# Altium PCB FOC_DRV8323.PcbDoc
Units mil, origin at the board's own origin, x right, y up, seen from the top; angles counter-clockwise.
Board outline 2192.91 x 943.98 mil, 4 copper layers (Top Layer, GND, Sign, Bottom Layer), stack 23.756 mil thick; 72 components, 67 nets, 296 pads, 257 vias.
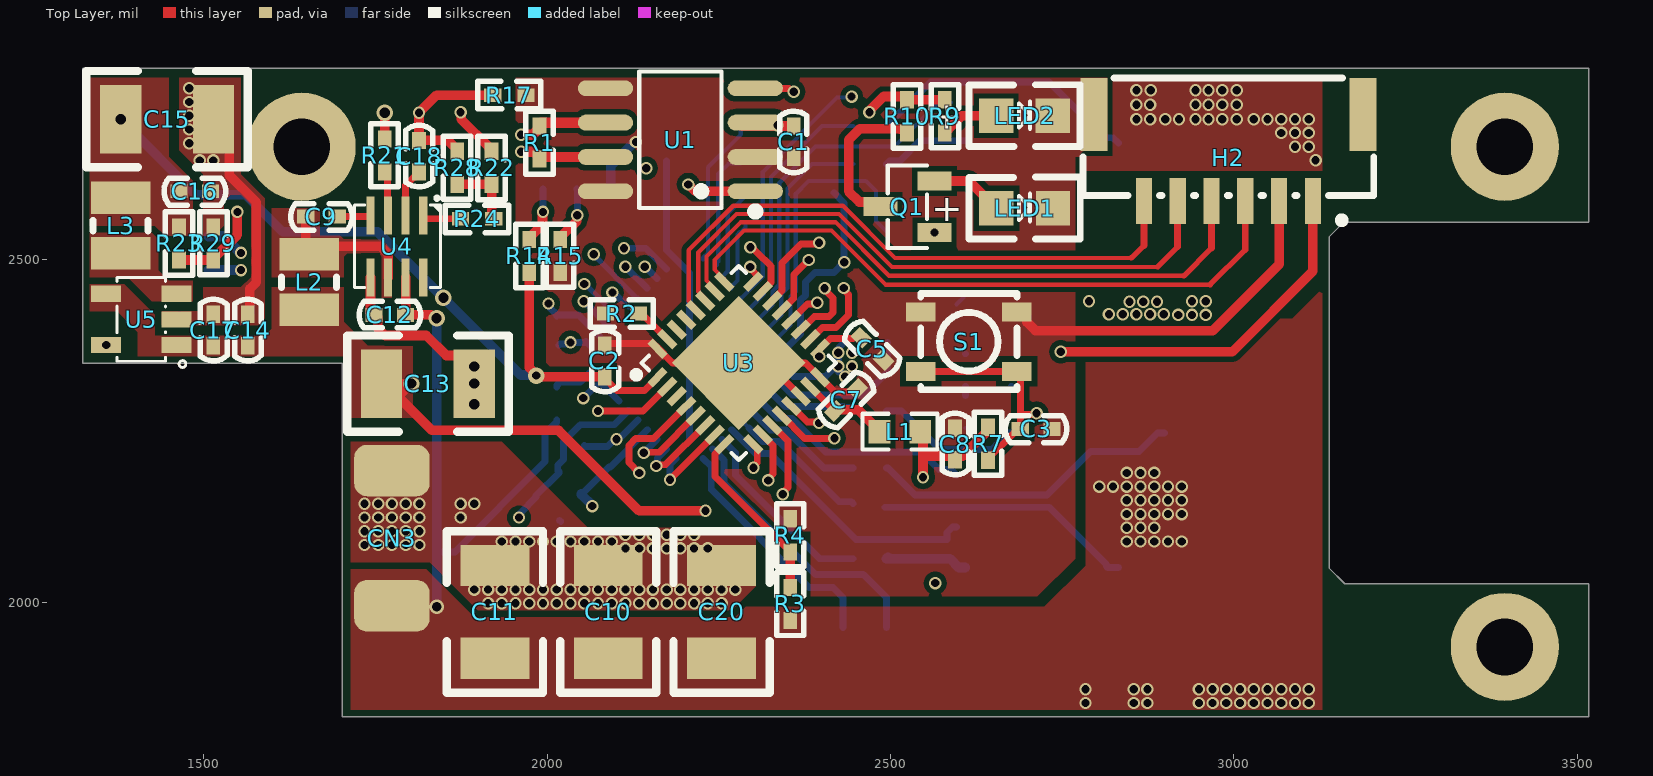
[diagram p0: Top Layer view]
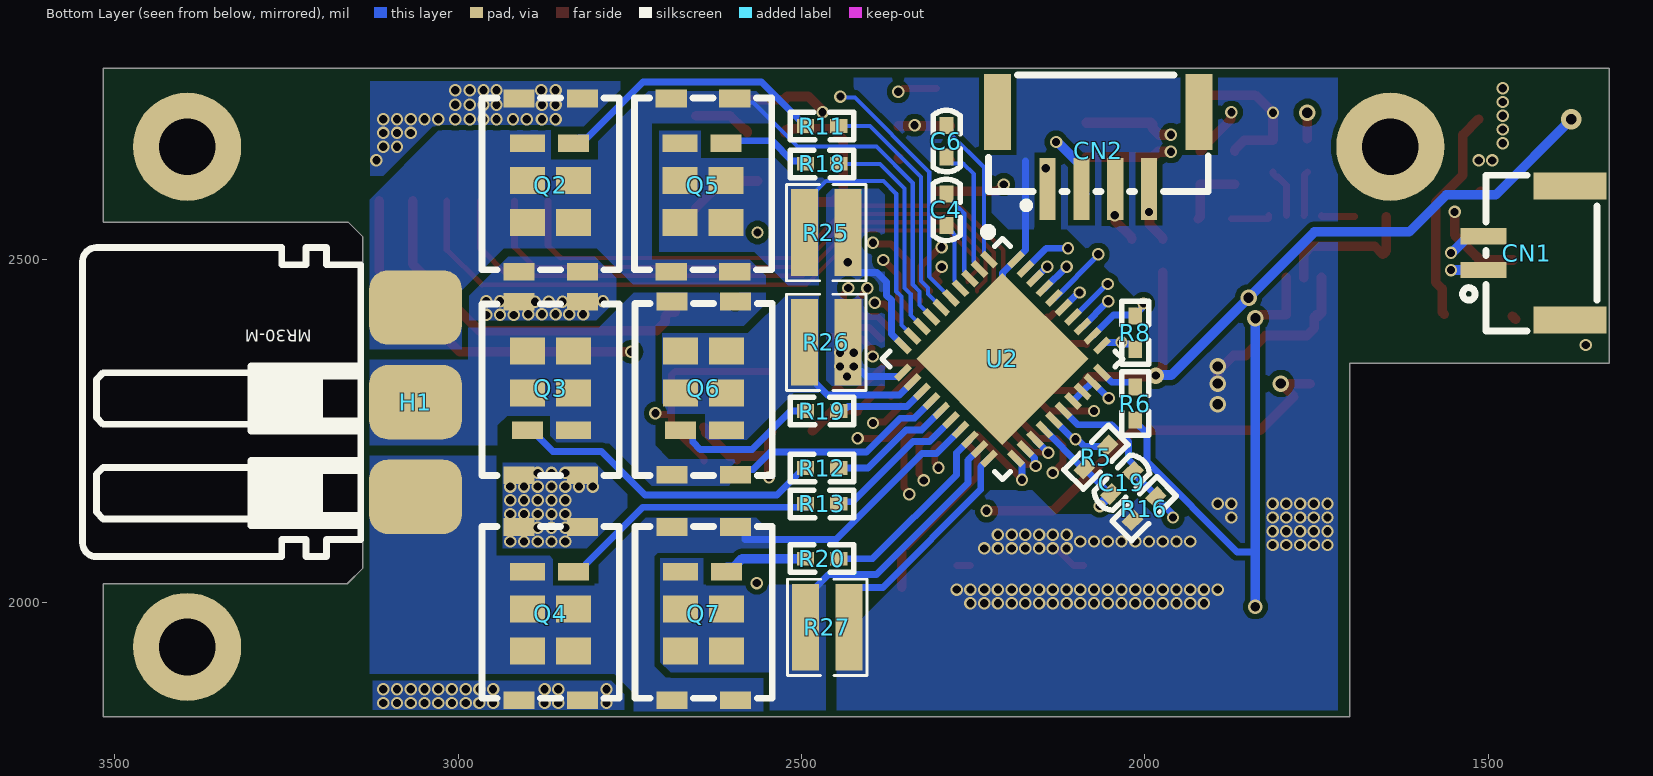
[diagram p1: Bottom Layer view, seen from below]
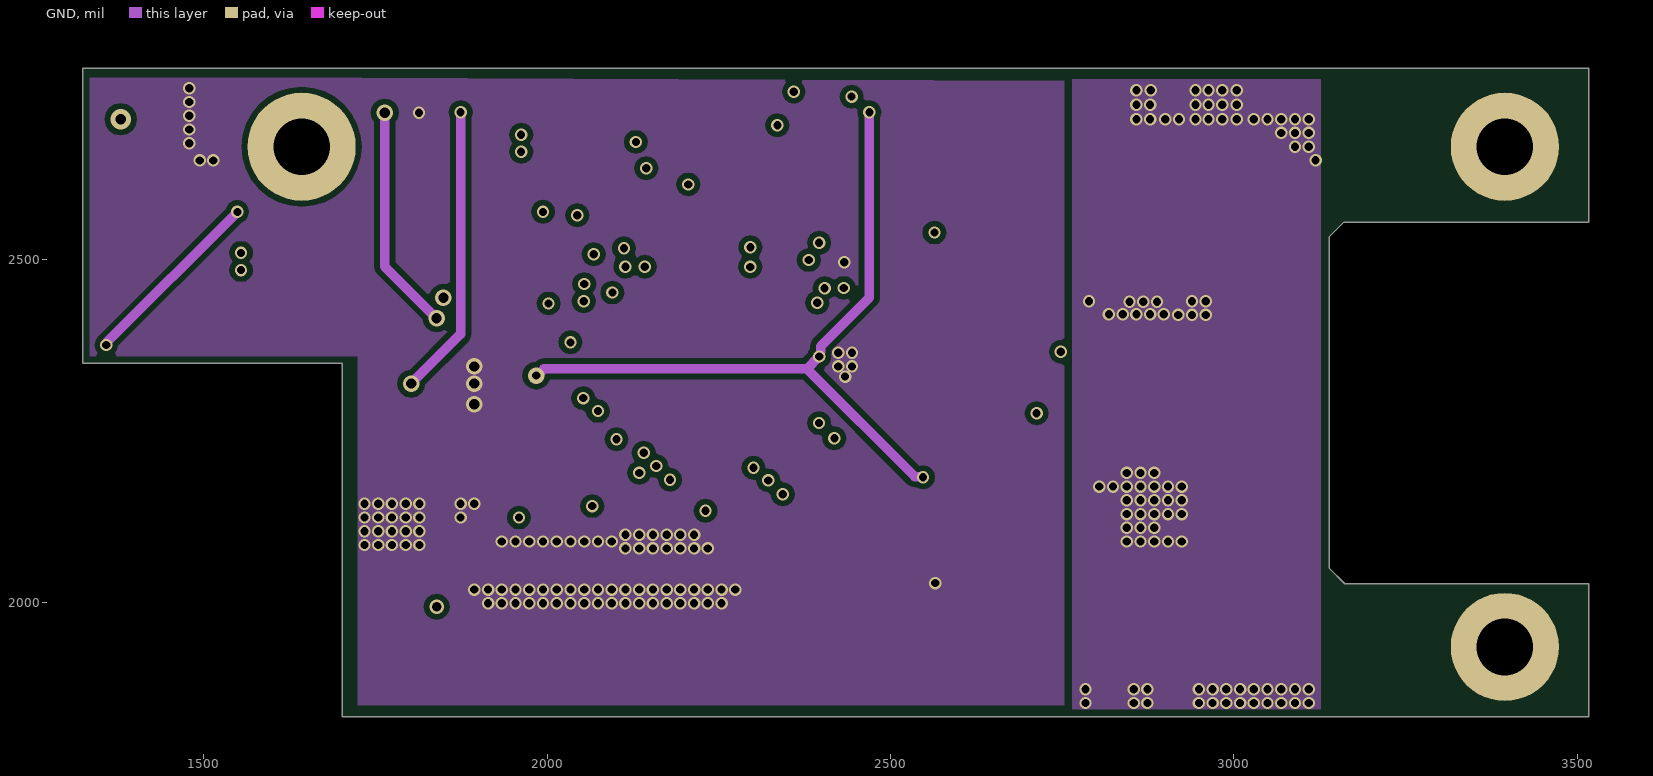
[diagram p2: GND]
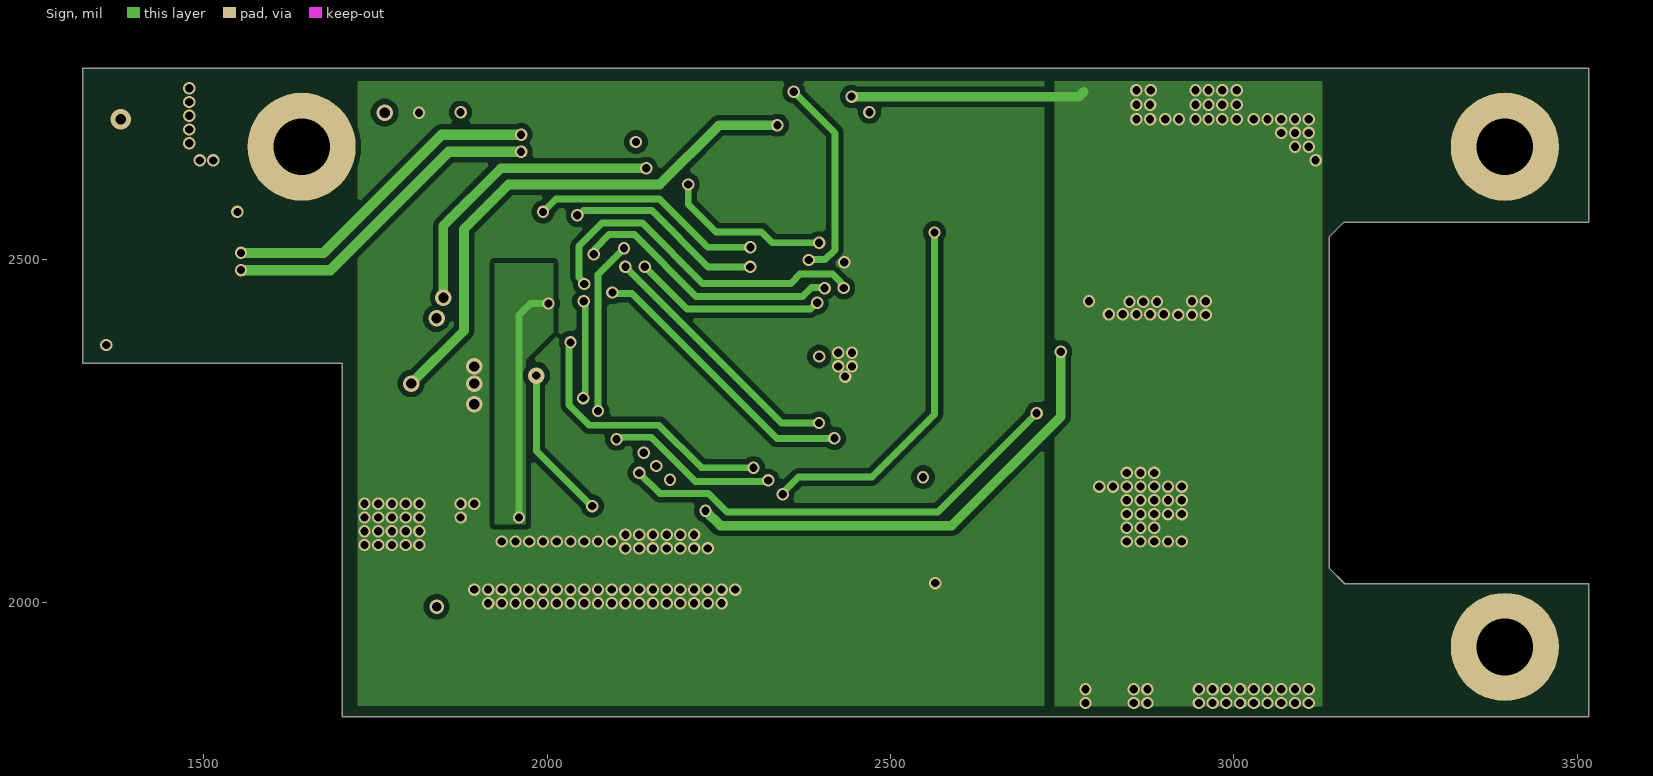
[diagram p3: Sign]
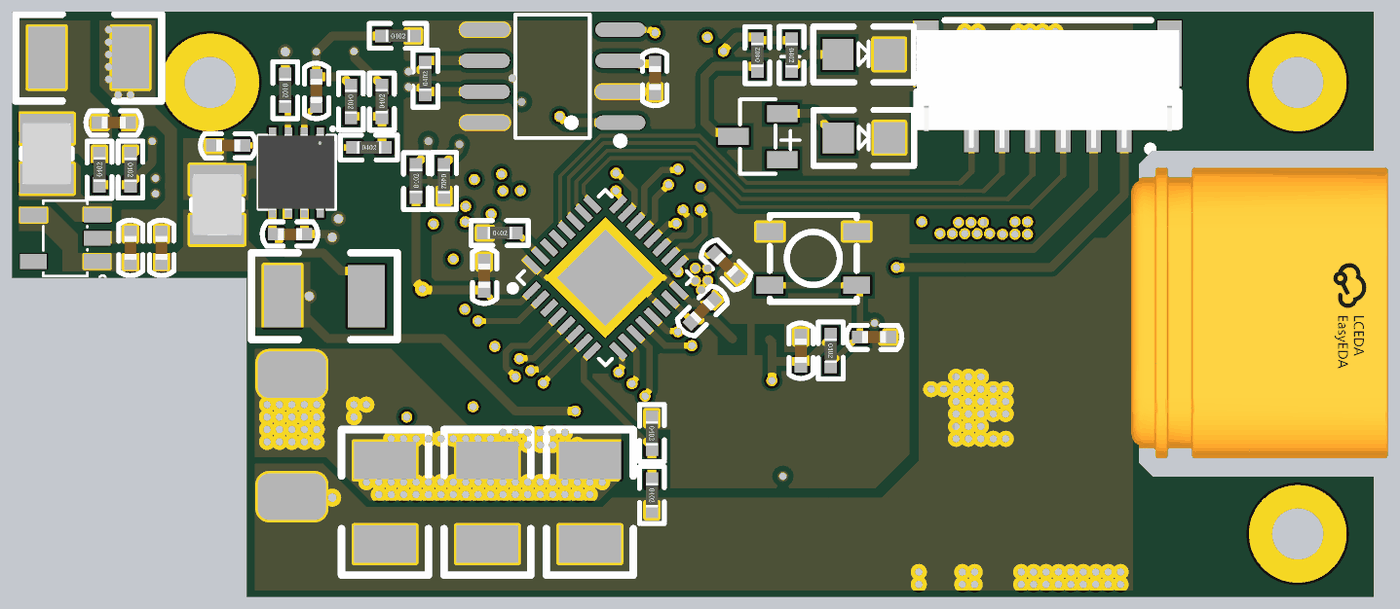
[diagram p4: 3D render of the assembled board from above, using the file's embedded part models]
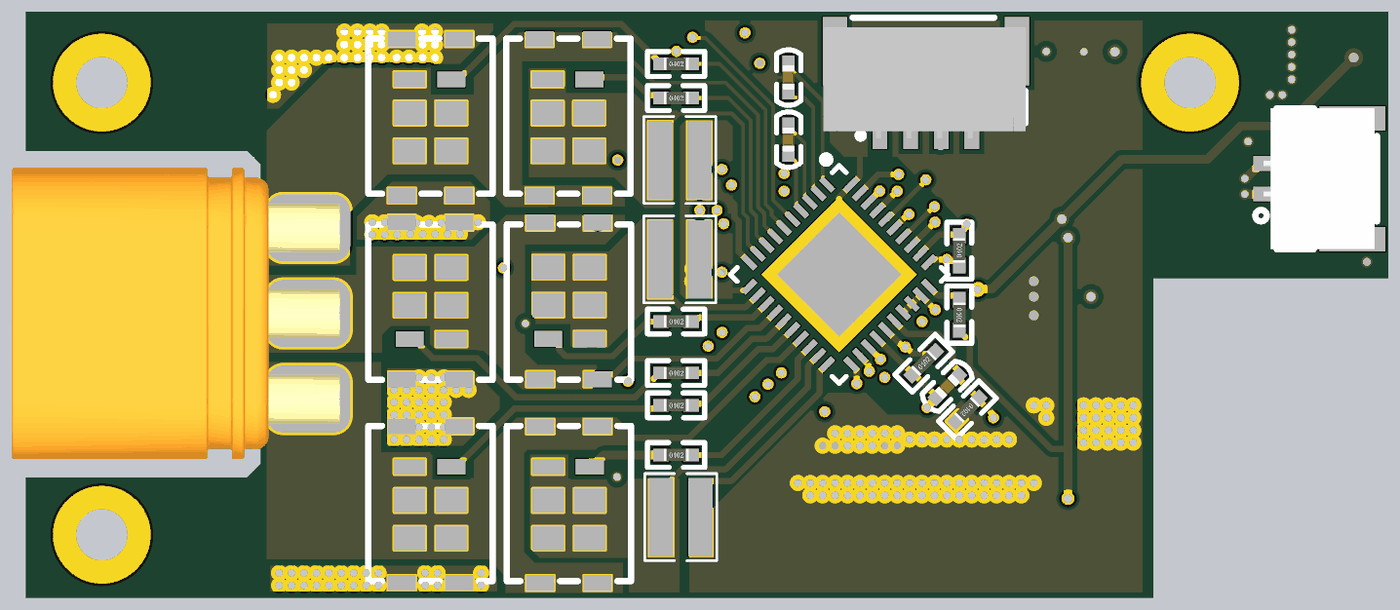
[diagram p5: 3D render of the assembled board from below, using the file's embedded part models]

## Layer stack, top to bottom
Top Solder: solder mask 0.4, Solder Resist, Dk 3.5
Top Layer: signal copper 1.4
Dielectric 2: prepreg 2.8, PP-006, Dk 4.1
GND: signal copper 1.378
Dielectric 1: dielectric 12.6, FR-4, Dk 4.8
Sign: signal copper 1.378
Dielectric 3: prepreg 2.8, PP-006, Dk 4.1
Bottom Layer: signal copper 1.4
Bottom Solder: solder mask 0.4, Solder Resist, Dk 3.5

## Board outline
1701.6,1834.03 1701.6,2348.88 1323.65,2348.88 1323.65,2778.02 3516.56,2778.02 3516.56,2553.61 3159.74,2553.61 3138.61,2532.47 3138.61,2050.37 3161.42,2027.56 3516.56,2027.56 3516.56,1834.03

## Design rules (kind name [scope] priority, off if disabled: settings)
Clearance [All] p1: gap=6 ignorepadtopadclearanceinfootprint=FALSE except(0: Arc-Hole Track-Hole SMDPad-Hole THPad-Hole Via-Hole Fill-Hole Poly-Hole Region-Hole Text-Hole; 8: Arc-Fill Arc-Poly Arc-Region Track-Fill Track-Poly Track-Region SMDPad-Fill SMDPad-Poly SMDPad-Region THPad-Fill THPad-Poly THPad-Region Via-Fill Via-Poly Via-Region Fill-Fill Fill-Poly Fill-Region Poly-Poly Poly-Region Region-Region)
DiffPairsRouting [All] p1: maxlimit=10 minlimit=10 mostfreqgap=10 toplayer_minwidth=15 toplayer_maxwidth=15 toplayer_prefwidth=15 midlayer1_minwidth=15 midlayer1_maxwidth=15 midlayer1_prefwidth=15 midlayer2_minwidth=15 midlayer2_maxwidth=15 midlayer2_prefwidth=15 bottomlayer_minwidth=15 bottomlayer_maxwidth=15 bottomlayer_prefwidth=15 maxuncoupledlength=500
HoleToHoleClearance [All] p1: gap=4 allowstackedmicrovias=TRUE
MinimumSolderMaskSliver [All] p1: minsoldermaskwidth=0
PlaneClearance [All] p1: clearance=8
PlaneConnect [All] p1: planeconnectstyle=Direct reliefexpansion=20 reliefentries=4 reliefconductorwidth=10 reliefairgap=10
PolygonConnect [All] p1: connectstyle=Direct reliefconductorwidth=10 reliefentries=4 polygonreliefangle="90 Angle" airgapwidth=10
RoutingVias [All] p1: holewidth=12 width=18 viastyle="Through Hole" minholewidth=10 minwidth=18 maxholewidth=28 maxwidth=50
SilkToSilkClearance [All] p1: silktosilkclearance=0
SilkToSolderMaskClearance [IsPad] p1: minsilkscreentomaskgap=0 clearancetoexposedcopper=TRUE
SolderMaskExpansion [All] p1: expansion=4 istentingtop=FALSE
Width [All] p1: maxlimit=14 minlimit=6 preferedwidth=10
23 further rules are at their usual default settings.

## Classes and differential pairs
differential pair CAN: +CAN_P -CAN_N

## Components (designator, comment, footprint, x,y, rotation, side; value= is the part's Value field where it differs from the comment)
C1 "100nF" c0402 2359,2649 r90 top
C2 "100nF" c0402 2084,2374 r270 top
C3 "100nF" c0402 2734,2253 r180 top
C4 "1uF" c0402 2289,2594.05 r270 bottom
C5 "100nF" c0402 2489,2354 r135 top
C6 "47nF" c0402 2289,2694 r270 bottom
C7 "100nF" c0402 2450.82,2310.82 r225 top
C8 "100nF" c0402 2594,2253 r270 top
C9 "100nF" c0402 1693.43,2562.19 r180 top
C10 "10uF" 1210 2089,2054 r270 top
C11 "10uF" 1210 1924,2054 r270 top
C12 "100nF" c0402 1749,2419 r0 top
C13 "10uF" 1210 1894,2319 r180 top
C14 "100nF" c0402 1564,2419 r270 top
C15 "10uF" 1210 1514,2704 r180 top
C16 "100nF" c0402 1509,2599 r180 top
C17 "1uF" c0402 1514,2419 r270 top
C18 "100nF" c0402 1813.43,2672.19 r270 top
C19 "100nF" c0402 2049,2159 r135 bottom
C20 "10uF" 1210 2254,2054 r270 top
CN1 "卧式CAN" "GH1.25 2P 卧式" 1444,2509 r90 bottom
CN2 "卧式STLINK" CONN-SMD_4P-P1.25_GH1.25-4P 2067.77,2658.35 r0 bottom
CN3 "XT30_1" XT30卧式焊盘 1774,2094 r0 top
H1 "MR30-M" MR30 3062,2292 r270 bottom
H2 "卧式GH1.25 6PIN" CONN-SMD_6P-P1.25_XYECONN_XY-GH1.25-6A61 2991.95,2648.1 r180 top
L1 "1008屏蔽电感" R0603 3878.19,2290.01 r180 top
L2 "1008屏蔽电感" IND-SMD_L2.5-W2.0 1653.43,2466.71 r90 top
L3 "1008屏蔽电感" IND-SMD_L2.5-W2.0 1379,2549 r270 top
LED1 "LED" led0805 2654.2,2574.35 r0 top
LED2 "LED" led0805 2654,2709 r0 top
Q1 "SS8050" SOT-23-3_L2.9-W1.3-P1.90-LS2.4-BR 2305.65,2731.51 r0 top
Q2 "IRF7480MTRPBF" TRS-SMD_IRF7480MTRPBF 2865.3,2607.9 r270 bottom
Q3 "IRF7480MTRPBF" TRS-SMD_IRF7480MTRPBF 2865.3,2312.03 r90 bottom
Q4 "IRF7480MTRPBF" TRS-SMD_IRF7480MTRPBF 2865.3,1983.98 r270 bottom
Q5 "IRF7480MTRPBF" TRS-SMD_IRF7480MTRPBF 2643.36,2607.9 r270 bottom
Q6 "IRF7480MTRPBF" TRS-SMD_IRF7480MTRPBF 2642.47,2312.31 r90 bottom
Q7 "IRF7480MTRPBF" TRS-SMD_IRF7480MTRPBF 2642.47,1983.98 r270 bottom
R1 "120Ω" R0402 1989,2645.8 r90 top
R2 "10K" R0402 2084.8,2421 r0 top
R3 "10K" R0402 2354,2022.2 r270 top
R4 "1K" R0402 2354,2122.2 r270 top
R5 "200k" R0402 2088.08,2194.92 r135 bottom
R6 "200k" R0402 2014,2314 r270 bottom
R7 "10K" R0402 2642,2255.5 r270 top
R8 "200k" R0402 2014,2369 r90 bottom
R9 "2K" R0402 2579,2732.2 r270 top
R10 "2KΩ" R0402 2524,2684 r90 top
R11 "2.2R" R0402 2494,2694 r180 bottom
R12 "2.2R" R0402 2494,2196.01 r180 bottom
R13 "2.2R" R0402 2494,2144 r180 bottom
R14 "10KΩ" R0402 1974,2480.8 r90 top
R15 "10KΩ" R0402 2019,2529 r270 top
R16 "0" R0402 1984,2154 r315 bottom
R17 "0" R0402 1920.8,2739 r0 top
R18 "2.2R" R0402 2494,2639 r180 bottom
R19 "2.2R" R0402 2494,2279 r180 bottom
R20 "2.2R" R0402 2494,2064 r180 bottom
R21 "10KΩ" R0402 1763.43,2675.39 r270 top
R22 "43KΩ" R0402 1919,2609 r90 top
R23 "232KΩ" R0402 1464,2499 r90 top
R24 "51KΩ" R0402 1874,2559 r0 top
R25 "0.001" R0612 2464,2539 r0 bottom
R26 "0.001" R0612 2464,2379 r0 bottom
R27 "0.001" R0612 2462.5,1964 r0 bottom
R28 "8.2KΩ" R0402 1869,2657.2 r270 top
R29 "51KΩ" R0402 1514,2547.2 r270 top
S1 "SW" KEY_SMD 2614,2380 r180 top
U1 "SN65HVD1050DR" SOIC-8_L4.9-W3.9-P1.27-LS6.0-BL 2194,2674 r90 top
U2 "DRV8323HRTAR" QFN-40_L6.0-W6.0-P0.50-BL-EP4.5 2215.52,2362.96 r315 bottom
U3 "STM32G431KBU3" UFQFPN-32_L5.0-W5.0-P0.50-BL-EP3.5 2275.98,2345.98 r315 top
U4 "MP9943" "QFN-8 3x3" 1819.59,2564 r270 top
U5 "TLV62569DBVR" SOT-23-5_L3.0-W1.7-P0.95-LS2.8-BR 1409,2409 r0 top

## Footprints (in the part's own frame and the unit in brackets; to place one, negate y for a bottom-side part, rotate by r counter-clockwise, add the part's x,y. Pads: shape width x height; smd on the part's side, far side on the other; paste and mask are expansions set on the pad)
1210 [mil]
  rect 60x100 smd: 1(0,0) 2(135,0)
  silkscreen extent -50,-70 185,70, body extent 4,-49 130,49, height 30
c0402 [mil]
  rect 25x20 smd: 1(-1,0) 2(45,0)
  silkscreen extent -23,-19 67,20, body extent 2,-10 42,10, height 20
CONN-SMD_4P-P1.25_GH1.25-4P [mm]
  rect 0.6x2.3 smd mask+0.051: 1(1.875,1.425) 2(0.625,1.425) 3(-0.625,1.425) 4(-1.875,1.425)
  rect 1x2.8 smd mask+0.051: 5(-3.725,-1.425) 6(3.725,-1.425)
  silkscreen extent -4.06,-2.8 4.06,2.16, body extent -4.07,-2.4 4.19,2.15, height 4.13
CONN-SMD_6P-P1.25_XYECONN_XY-GH1.25-6A61 [mm]
  rect 0.6x1.7 smd paste+0 mask+0.05: 1(-3.125,1.6) 2(-1.875,1.6) 3(-0.625,1.6) 4(0.625,1.6) 5(1.875,1.6) 6(3.125,1.6)
  rect 1x2.7 smd paste+0 mask+0.05: 7(4.975,-1.6) 8(-4.975,-1.6)
  silkscreen extent -5.38,-2.95 5.38,2.44, body extent -5.38,-2.55 5.39,2.3, height 4.34
"GH1.25 2P 卧式" [mm]
  rect 0.6x1.7 smd mask+0.051: 1(-0.625,1.602) 2(0.625,1.602)
  rect 1x2.7 smd mask+0.051: 3(2.475,-1.602) 4(-2.475,-1.598)
  silkscreen extent -2.88,-2.6 2.88,2.37, body extent -2.88,-2.51 2.88,2.05, height 4.13
IND-SMD_L2.5-W2.0 [mm]
  rect 1.2x2.2 smd: 1(1.028,0) 2(-1.028,0)
  silkscreen extent -0.2,-1.02 0.2,1.02, body extent -1.26,-1 1.26,1, height 1.2
KEY_SMD [mm]
  rect 1.1x0.7 smd: 1(-1.775,-1.1) 1(1.775,-1.1) 2(-1.775,1.1) 2(1.775,1.1)
  silkscreen extent -1.78,-1.78 1.78,1.78
led0805 [mil] "1/8W"
  rect 50x50 smd: 1(0,0) 2(82.3,0.2)
  silkscreen extent -40,-45 122,45, body extent 2,-25 80,25, height 20
MR30 [mm]
  rrect50% 2.75x3.429 smd: 1(3.5,0) 2(0,0) 3(-3.5,0)
  silkscreen extent -5.72,-12.31 5.71,-2.02, body extent -5.95,-12.12 5.95,1.28, height 2.45
"QFN-8 3x3" [mm]
  rect 1.4x0.3 smd: 1(0,0) 2(0,-0.65) 3(0,-1.3) 4(0,-1.95) 5(2.3,-1.95) 6(2.3,-1.3) 7(2.3,-0.65) 8(2.3,0)
  silkscreen extent -0.64,-2.54 2.67,0.64, body extent -0.41,-2.53 2.69,0.57, height 0.94
QFN-40_L6.0-W6.0-P0.50-BL-EP4.5 [mm]
  rect 0.25x0.7 smd paste-100 mask+0.051: 1(-2.25,-2.659) 2(-1.75,-2.659) 3(-1.25,-2.659) 4(-0.75,-2.659) 5(-0.25,-2.659) 6(0.25,-2.659) 7(0.75,-2.659) 8(1.25,-2.659) 9(1.75,-2.659) 10(2.25,-2.659) 21(2.25,3.241) 22(1.75,3.241) 23(1.25,3.241) 24(0.75,3.241) 25(0.25,3.241) 26(-0.25,3.241) 27(-0.75,3.241) 28(-1.25,3.241) 29(-1.75,3.241) 30(-2.25,3.241)
  rect 0.7x0.25 smd paste-100 mask+0.051: 11(2.95,-1.958) 12(2.95,-1.459) 13(2.95,-0.958) 14(2.95,-0.459) 15(2.95,0.042) 16(2.95,0.541) 17(2.95,1.042) 18(2.95,1.541) 19(2.95,2.041) 20(2.95,2.541) 31(-2.95,2.541) 32(-2.95,2.041) 33(-2.95,1.541) 34(-2.95,1.042) 35(-2.95,0.541) 36(-2.95,0.042) 37(-2.95,-0.459) 38(-2.95,-0.958) 39(-2.95,-1.459) 40(-2.95,-1.958)
  rect 4.5x4.5 smd paste-100 mask+0.051: 41(0,0.292)
  silkscreen extent -3.15,-3.56 3.15,3.44
R0402 [mil] "1/16W"
  rect 25x20 smd: 1(0,0) 2(48.2,0)
  silkscreen extent -22,-20 70,20, body extent 5,-10 44,10, height 14
R0603 [mil]
  rect 31.75x34.02 smd paste-3937.01 mask+2: 1(1334.87,41.01) 2(1394.19,41.01)
  silkscreen extent 1310,15 1419,67, body extent 1334,24 1396,56, height 18
R0612 [mm]
  rect 1x3.2 smd paste+0 mask+0.051: 1(-0.8,0) 2(0.8,0)
  silkscreen extent -1.47,-1.78 1.47,1.78
SOIC-8_L4.9-W3.9-P1.27-LS6.0-BL [mm]
  oval 0.588x2.045 smd mask+0.051: 1(-1.905,-2.772) 2(-0.635,-2.772) 3(0.635,-2.772) 4(1.905,-2.772) 5(1.905,2.772) 6(0.635,2.772) 7(-0.635,2.772) 8(-1.905,2.772)
  silkscreen extent -2.8,-2.92 2.53,1.52, body extent -2.45,-3 2.45,3, height 1.75
SOT-23-3_L2.9-W1.3-P1.90-LS2.4-BR [mm]
  rect 1.25x0.7 smd: 1(6.562,-4.885) 2(6.562,-2.985) 3(4.562,-3.935)
  silkscreen extent 4.84,-5.46 6.29,-2.41, body extent 4.19,-5.39 6.99,-2.49, height 1.3
SOT-23-5_L3.0-W1.7-P0.95-LS2.8-BR [mm]
  rect 1.1x0.6 smd paste+0 mask+0.051: 1(1.3,-0.861) 2(1.3,0.089) 3(1.3,1.039) 4(-1.3,1.039) 5(-1.3,-0.861)
  silkscreen extent -0.9,-1.69 1.65,1.64
TRS-SMD_IRF7480MTRPBF [mm]
  rect 0.65x1.15 smd paste+0 mask+0.051: 1(-1.555,0.85) 7(-3.205,1.175) 8(-3.205,-1.175) 9(3.205,-1.175) 10(3.205,1.175)
  rect 1x1.3 smd paste+0 mask+0.051: 2(-0.175,0.85) 3(1.375,0.85) 4(1.375,-0.85) 5(-0.175,-0.85)
  rect 0.65x1.3 smd paste+0 mask+0.051: 6(-1.555,-0.85)
  silkscreen extent -3.22,-2.54 3.13,2.54
UFQFPN-32_L5.0-W5.0-P0.50-BL-EP3.5 [mm]
  rect 0.28x0.8 smd paste-100 mask+0.051: 1(-1.75,-2.392) 2(-1.25,-2.392) 3(-0.75,-2.392) 4(-0.25,-2.392) 5(0.25,-2.392) 6(0.75,-2.392) 7(1.25,-2.392) 8(1.75,-2.392) 17(1.75,2.609) 18(1.25,2.608) 19(0.75,2.609) 20(0.25,2.608) 21(-0.25,2.608) 22(-0.75,2.608) 23(-1.25,2.608) 24(-1.75,2.608)
  rect 0.8x0.28 smd paste-100 mask+0.051: 9(2.5,-1.642) 10(2.5,-1.142) 11(2.5,-0.642) 12(2.5,-0.142) 13(2.5,0.358) 14(2.5,0.858) 15(2.5,1.358) 16(2.5,1.858) 25(-2.5,1.858) 26(-2.5,1.358) 27(-2.5,0.858) 28(-2.5,0.358) 29(-2.5,-0.142) 30(-2.5,-0.642) 31(-2.5,-1.142) 32(-2.5,-1.642)
  rect 3.5x3.5 smd paste-100 mask+0.051: 33(0,0.108)
  silkscreen extent -2.54,-3.01 2.54,2.65
XT30卧式焊盘 [mil]
  rrect50% 110x75 smd: 1(0,98.43) 2(0,-98.43)

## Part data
C1 C9 C12 C14 C15 C16 C17 C18: library part 0402贴片电容, "贴片电容0402"
C2 C3 C4 C5 C6 C7 C8 C19: library part CC0201JRX7R9BB101
C10 C11 C13 C20: library part 1210贴片电容, "1210贴片电容"
H1: BOM_Manufacturer=AMASS(艾迈斯)
LED1 LED2: library part 0805贴片LED, "0805贴片LED"
Q1: library part 2N2222, "三极管"
R1 R10 R14 R15 R21 R22 R23 R24 R28 R29: library part 0402贴片电阻, "0402贴片电阻"
R2 R3 R4 R5 R6 R7 R8 R9 R16 R17: library part 2.2R, BOM_Manufacturer=UniOhm, BOM_Manufacturer Part=0603WAJ022JT5E
R11 R12 R13 R18 R19 R20: BOM_Manufacturer=UniOhm, BOM_Manufacturer Part=0603WAJ022JT5E
R25 R26 R27: library part 0.0005, BOM_Manufacturer=RALEC(旺诠), BOM_Manufacturer Part=LR2512-23R0005J4
S1: "开关"
U1: "CAN芯片", JLCPCB Part Class="Extended Part", LCSC Part Name=4.5V~5.5V, Manufacturer=TI(德州仪器), Operating Temperature=-40℃~+125℃, Supply Current=50mA

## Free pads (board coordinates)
  round 157.48 hole 82.68: 2(1642.54,2663.84) 2(3394.51,1935.5) 2(3394.51,2663.84)

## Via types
v1: diameter 18, hole 12, Top Layer to Bottom Layer, 226 vias
v2: diameter 18, hole 12, Top Layer to Bottom Layer, tented both sides, 21 vias
v3: diameter 24, hole 15, Top Layer to Bottom Layer, tented both sides, 7 vias
v4: diameter 24, hole 12, Top Layer to Bottom Layer, 1 vias
v5: diameter 30, hole 15, Top Layer to Bottom Layer, tented both sides, 1 vias
v6: diameter 21, hole 14, Top Layer to Bottom Layer, 1 vias

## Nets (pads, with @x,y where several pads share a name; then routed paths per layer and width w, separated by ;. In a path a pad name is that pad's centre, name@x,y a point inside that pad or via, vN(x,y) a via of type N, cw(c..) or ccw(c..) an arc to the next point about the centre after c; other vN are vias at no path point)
5V: C1.2 C13.2 C14.2 C17.2 H2.1 L2.2 R22.2 U1.3 U5.1 U5.4 | length 3195.3
  Top Layer w10: U1.3@2283.15,2694 2283.7,2694.55 2334.73,2694.55 v1(2335.28,2695.09)
  Top Layer w14: C13.2 v3(1802.04,2319) 1783.02,2299.98 1832.12,2250.88 2016.84,2250.88 2134.03,2133.69 v1(2230.64,2133.69) ; v2(1874,2714) 1874.77,2713.23 1874.77,2703.93 1916,2662.7 1916,2660.2 R22.2 ; U1.3@2283.15,2694 C1.2 ; v1(2747.98,2365.33) 2997.57,2365.33 3114.98,2482.74 H2.1
  GND w14: v3(1802.04,2319) 1874,2390.96 v2(1874,2714)
  Sign w14: v3(1802.04,2319) 1879,2395.96 1879,2544 1943.83,2608.83 2163.91,2608.83 2250.18,2695.09 v1(2335.28,2695.09) ; v1(2230.64,2133.69) 2252.17,2112.16 2589.16,2112.16 2747.98,2270.98 v1(2747.98,2365.33)
+3.3V: C2.2 C5.2 C8.2 C15.2 C16.2 C19.1 CN2.1 L1.1 L3.2 R5.1 R7.1 R9.1 R10.2 R14.1 R23.2 U2.24 U3.1 U3.17 | length 3341.7
  Top Layer w10: C2.2@2084,2326.5 2101.5,2309 2141.56,2309 U3.1 ; U3.17 2398.04,2369.89 2412.7,2384.55 2445.31,2384.55 2448.34,2387.59 2455.41,2387.59 C5.2
  Top Layer w14: R14.1 1974,2342.04 1984.25,2331.79 v4(1984.25,2330.71) 1985.33,2330.71 1987.04,2329 2081,2329 2083.5,2326.5 C2.2@2084,2326.5 ; v1(2469.26,2714.24) 2470.02,2715.01 2470.02,2717.14 2489.89,2737 2521,2737 2524,2734 R10.2 R9.1 ; L1.1 2547.33,2244.99 2547.33,2213.5 ; v1(2547.33,2182.76) 2547.33,2213.5 ; C8.2 C8.2@2594,2210.5 ; R7.1 2639,2252.5 2639,2247.5 2605,2213.5 2597,2213.5 C8.2@2594,2210.5 ; 2547.33,2213.5 2591,2213.5 C8.2@2594,2210.5
  GND w14: v4(1984.25,2330.71) 1985.33,2330.71 1995.2,2340.57 2378.22,2340.57 ; v1(2396.12,2358.47) 2378.22,2340.57 ; v1@2398.58,2364.74 2398.58,2373.58 2469.26,2444.26 v1@2469.26,2713.63 ; v1(2547.33,2182.76) 2546.56,2183.53 2535.26,2183.53 2378.22,2340.57
  Sign w10: v4(1984.25,2330.71) 1984.25,2220.96 2064.55,2140.66 v1(2065.86,2140.66)
  Sign w14: v3(1849,2444) 1849,2549 1932.45,2632.45 v2(2144.17,2632.45)
  Bottom Layer w10: C19.1 2050.58,2158.29 2089.94,2197.65 2091.97,2197.65 U2.24
  Bottom Layer w14: v5(1379,2704) 1489,2594 1561,2594 1615,2540 1753,2540 1961.53,2331.47 1983.49,2331.47 v4(1984.25,2330.71) ; C19.1 2049.71,2157.56 2065.86,2141.4 v1(2065.86,2140.66)
AGND: C19.2 R8.2 R16.1 U2.26 U2.32 | length 696.5
  Sign w10: v1(1959,2124) 1959,2419 1975.65,2435.65 v1(2002.06,2435.65)
  Bottom Layer w10: v1(1959,2124) 1960.15,2125.15 1960.15,2130.15 R16.1 1984,2155.82 2017.18,2189 C19.2 2015.41,2192.59 2015.41,2199.66 2024.08,2208.33 2024.08,2234.93 2048.15,2259 2097.64,2259 U2.26 ; v1(2002.06,2435.65) 2003.59,2434.12 2003.59,2430.11 2014,2419.7 R8.2 2015.8,2419 2045.81,2419 U2.32
CAL: R8.1 U2.31 U3.9 | length 488.7
  Top Layer w10: U3.9 2307.11,2223.43 2307.11,2222.71 2305.99,2221.59 2305.99,2204.2 2300.43,2198.63 v1(2300.43,2196.47)
  Sign w10: v1(2034,2379) 2032.47,2377.47 2032.47,2371.81 2032.02,2371.36 2032.02,2288.17 2061.92,2258.27 2163.24,2258.27 2225.04,2196.47 v1(2300.43,2196.47)
  Bottom Layer w10: R8.1@2017.41,2374.91 2019,2376.5 2029.88,2376.5 2033.86,2380.49 v1@2034,2380.49 ; v1(2034,2379) 2054.89,2379 2056.38,2380.49 2056.49,2380.49 U2.31
CAN_N: CN1.2 R1.2 U1.6 | length 669.6
  Top Layer w15: v2(1962.09,2681.5) 1979,2681.5 1989,2691.5 R1.2 1989,2696.5 1991.5,2699 U1.6
  Sign w15: v2(1554.32,2509.29) 1566.79,2509.29 1567.04,2509.05 1674,2509.05 1846.45,2681.5 v2(1962.09,2681.5)
  Bottom Layer w15: CN1.2 1528.72,2533.61 1552.46,2509.87 1553.74,2509.87 v2(1554.32,2509.29)
CAN_P: CN1.1 R1.1 U1.7 | length 656.3
  Top Layer w15: v2(1962.09,2656.5) 1980.8,2656.5 1989,2648.3 R1.1@1989,2646.5 ; R1.1 R1.1@1989,2646.5 ; U1.7 1991.5,2649 R1.1@1989,2646.5
  Sign w15: v2(1554.32,2484.29) 1554.56,2484.05 1684.36,2484.05 1856.81,2656.5 1949.61,2656.5 v2(1962.09,2656.5)
  Bottom Layer w15: CN1.1 1507.12,2484.34 v2(1554.32,2484.29) v2(1554.32,2484.29)
DGND: C1.1 C2.1 C3.1 C5.1 C7.1 C8.1 CN2.2 H2.2 H2.7 LED1.2 LED2.2 R2.1 R4.1 R15.2 R17.2 S1.1 U1.2 U1.5 U1.8 U3.14 U3.16 U3.32 U3.33 | length 1099.2
  Top Layer w10: C2.1@2084.9,2375.9 2086.12,2377.12 2153.44,2377.12 U3.32 2161.41,2369.88 2182.29,2349 U3.33 U3.33@2320.75,2349 ; U3.14 U3.33@2320.75,2349 ; C7.1 2444.46,2311.53 2439.9,2306.97 2419.18,2306.97 2398.04,2328.11 U3.16 2376.43,2349 U3.33@2320.75,2349 ; C5.1@2489.71,2351.5 C5.1
  Top Layer w14: U1.2@2283.15,2644 U1.2@2284.9,2645.75 ; C1.1@2356.75,2645.75 C1.1 ; S1.1@2683.88,2423.3 2691.76,2423.3 2698.54,2416.52 2698.54,2408.65 2711.06,2396.13 2969.32,2396.13 3065.77,2492.59 H2.2
  Bottom Layer w10: CN2.2@2085.57,2595.44 CN2.2
  Bottom Layer w14: CN2.2 2092.38,2635.72 2126.7,2670.04 2128.49,2670.04 v2(2129.26,2670.8)
DVDD: U2.27 U2.28 U2.29 U2.33 | length 260
  Sign w10: v1(2052.64,2297.87) 2054.18,2299.4 2054.18,2305.06 2055.44,2306.32 2055.44,2434.56 2053.17,2436.84 v1(2053.17,2439)
  Bottom Layer w10: v1(2052.64,2297.87) 2052.88,2297.87 U2.29@2070.3,2315.29 ; v1(2053.17,2439) 2053.55,2439 2090.37,2402.17 U2.33 ; U2.29 U2.28 U2.27
FDCAN_RX: U1.4 U3.21 | length 447
  Top Layer w10: U1.4 2303.42,2748.73 2352.11,2748.73 2356.84,2744 v1(2359,2744) ; U3.21 2359,2442.93 2359,2477.06 v1(2380.85,2498.91)
  Sign w10: v1(2359,2744) 2419,2684 2419,2513.59 2404.85,2499.44 2381.38,2499.44 v1(2380.85,2498.91)
FDCAN_TX: U1.1 U3.22 | length 471.8
  Top Layer w10: U3.22 2327.71,2440.2 2341.91,2454.39 2341.91,2494.75 2369.63,2522.47 2394.47,2522.47 v1(2396,2524)
  Top Layer w14: v1(2205.45,2608.98) 2205.67,2608.98 2215.65,2599 U1.1
  Sign w10: v1(2205.45,2608.98) 2205.45,2580.23 2245.68,2540 2312,2540 2328,2524 v1(2396,2524)
M0_AH: U2.34 U3.18 | length 692.7
  Top Layer w10: U3.18 2384.12,2383.8 2400.87,2400.55 2420.55,2400.55 2439,2419 2439,2448.9 2431.85,2456.06 v1(2431.85,2458.22)
  Sign w10: v1(2054,2464) 2054,2466.16 2046.44,2473.72 2046.44,2519.35 2079.73,2552.63 2138.82,2552.63 2226.46,2465 2355,2465 2368.41,2478.41 2415.35,2478.41 2427.85,2465.91 2427.85,2464.39 2431.85,2460.39 v1(2431.85,2458.22)
  Bottom Layer w6: v1(2054,2464) v1@2055.24,2464 ; U2.34@2103.16,2416.09 U2.34
  Bottom Layer w8: v1@2055.24,2464 U2.34@2103.16,2416.09
M0_AL: U2.35 U3.12 | length 524.9
  Top Layer w10: U3.12 2374.81,2239.27 v1(2418.27,2239.27)
  Sign w10: v1(2095.05,2451.56) 2096.58,2450.03 2123.62,2450.03 2334.38,2239.27 v1(2418.27,2239.27)
  Bottom Layer w10: v1(2095.05,2451.56) 2096.66,2451.56 U2.35@2112.06,2436.16
M0_BH: U2.36 U3.19 | length 584
  Top Layer w10: U3.19 2370.2,2397.73 2389.02,2416.55 2410.56,2416.55 2416.42,2422.41 2416.42,2443.5 2404,2455.91 v1(2404,2458)
  Sign w6: v1@2403,2459 v1(2404,2458)
  Sign w10: v1(2067.98,2507.28) 2069.51,2508.81 2069.51,2515.28 2090.31,2536.08 2126.92,2536.08 2217,2446 2371.84,2446 2384.84,2459 v1@2403,2459
  Bottom Layer w6: v1@2067.98,2505.98 v1(2067.98,2507.28) ; U2.36@2130.03,2443.93 U2.36
  Bottom Layer w8: v1@2067.98,2505.98 U2.36@2130.03,2443.93
M0_BL: U2.37 U3.13 | length 471.8
  Top Layer w10: U3.13 2378.78,2263.12 2394.39,2263.12 v1(2395.92,2261.58)
  Sign w10: v1(2114,2489) 2341.42,2261.58 v1(2395.92,2261.58)
  Bottom Layer w6: U2.37@2145.66,2457.85 U2.37
  Bottom Layer w10: v1(2114,2489) 2145.15,2457.85 U2.37@2145.66,2457.85
M0_CH: U2.38 U3.20 | length 353.7
  Top Layer w10: U3.20 2378.94,2435.02 2391.7,2435.02 v1(2393.23,2436.55)
  Sign w10: v1(2142.05,2489.23) 2203.73,2427.55 2383.37,2427.55 2392.37,2436.55 v1(2393.23,2436.55)
  Bottom Layer w6: U2.38@2159.8,2471.77 U2.38
  Bottom Layer w10: v1(2142.05,2489.23) 2142.33,2489.23 U2.38@2159.8,2471.77
M0_CL: U2.39 U3.2 | length 442.6
  Top Layer w10: v1(2074,2279) 2139.41,2279 U3.2
  Sign w10: v1(2074,2279) 2074,2478.16 v1(2111.84,2516)
  Bottom Layer w10: v1(2111.84,2516) 2143.69,2516 U2.39
M0_GH_A: R11.2 U2.6 | length 352.5
  Bottom Layer w6: U2.6 2316.02,2449.54 2316.02,2458.23 2326,2468.21 2326,2619.66 2400.34,2694 R11.2
M0_GH_B: R12.2 U2.15 | length 184
  Bottom Layer w10: U2.15 2324.94,2251.22 2347.9,2251.22 2403.11,2196.01 R12.2
M0_GH_C: R13.2 U2.16 | length 213.7
  Bottom Layer w6: U2.16@2282.57,2265.72 2294,2254.29
  Bottom Layer w10: 2294,2254.29 2313.86,2234.44 2337.56,2234.44 2425.04,2146.96 2442.84,2146.96 R13.2
M0_GL_A: R18.2 U2.8 | length 322.4
  Bottom Layer w6: U2.8 2340.97,2418.82 2340.97,2449.25 2350,2458.27 2350,2603.33 2385.67,2639 R18.2
M0_GL_B: R19.2 U2.13 | length 133.3
  Bottom Layer w10: U2.13 2324.44,2307.52 2346.44,2285.51 2432.44,2285.51 2433.96,2284 2440.8,2284 R19.2
M0_GL_C: R20.2 U2.18 | length 282
  Bottom Layer w10: U2.18 2274.42,2218.24 2274.42,2185.97 2396.39,2064 R20.2
M0_SH_A: H1.3 Q2.2 Q2.3 Q2.4 Q2.5 Q2.6 Q5.7 Q5.8 Q5.9 Q5.10 U2.7 | length 504.9
  Bottom Layer w6: U2.7 2328.02,2433.69 2328.02,2453.26 2338,2463.24 2338,2611.32 2390.68,2664 2505.97,2664 2570.26,2728.3 Q5.7@2587.78,2728.3
M0_SH_B: H1.2 Q3.2 Q3.3 Q3.4 Q3.5 Q3.6 Q6.7 Q6.8 Q6.9 Q6.10 U2.14 | length 344.2
  Bottom Layer w6: Q6.9@2596.21,2434.49 Q6.9@2606.01,2444.28
  Bottom Layer w10: U2.14 2335.41,2268.6 2356.11,2268.6 2405.45,2219.27 2544.93,2219.27 2570.28,2193.92 2588.41,2193.92 Q6.8
M0_SH_C: H1.1 Q4.2 Q4.3 Q4.4 Q4.5 Q4.6 Q7.7 Q7.8 Q7.9 Q7.10 U2.17 | length 407.7
  Bottom Layer w10: U2.17 2303.49,2217 2324.31,2217 2449.58,2091.74 2582.26,2091.74 2582.26,2102.37 2590.06,2110.16 Q7.7
M0_SNA: C10.1 C11.1 C12.1 C13.1 C14.1 C15.1 C16.1 C17.1 C18.1 C20.1 CN3.1 R16.2 R17.1 R25.1 R26.1 R27.1 R28.1 R29.1 U2.10 U2.11 U2.20 U2.40 U2.41 U4.5 U5.2 | length 2076
  Top Layer w10: C10.1 2104,2054 C10.1@2129,2079 ; C20.1 C20.1@2274,2054
  Top Layer w14: U5.2 U5.2@1464.99,2417.31 ; C16.1 1511,2599 C16.1@1514,2596 ; C15.1 1537,2681 1537,2622.63 1576.44,2583.2 1576.44,2466.44 1567,2457 1567,2423 C14.1 ; U4.5 1742.82,2422 1748.82,2416 C12.1@1753.1,2416 ; C12.1 1750.1,2419 C12.1@1753.1,2416 ; R28.1 1869,2659.7 1855.51,2673.19 C18.1 v2(1813.43,2713.43) 1839,2739 R17.1 ; v3(1894,2319) 1894,2336.85 1871,2359.85 1853.15,2359.85 1824,2389 1764,2389 1753.1,2399.9 C12.1@1753.1,2416
  Bottom Layer w10: R16.2 R16.2@2019.85,2118.15 ; 2174,2642.89 2174,2513.52 U2.40 2207.4,2480.12 U2.41 U2.41@2207.4,2236.64 ; U2.20 2239,2197.98 2239,2164.55 2381.56,2021.99 2416.32,2021.99 2431.01,2007.31 R27.1 ; U2.10 2369,2391.17 2369,2440.5 2376,2447.5 2376,2467 2390.02,2481.02 2417.82,2481.02 v1(2432.5,2495.71) 2432.5,2582.22 R25.1@2417.82,2596.91 ; U2.11@2358.43,2329.2 2405.56,2329.2 R26.1@2424,2347.64 ; R26.1 2424,2370.5 v1(2424,2364) R26.1@2424,2347.64 ; v1(2433.82,2329.18) 2427.28,2335.72 2424,2335.72 v1(2424,2344) 2425,2345 2424,2346 R26.1@2424,2347.64
  other v1: 1914,1999 1934,1999 1954,1999 1974,1999 1994,1999 2014,1999 2034,1999 2054,1999 2074,1999 2094,1999 2114,1999 2134,1999 2154,1999 2174,1999 2194,1999 2214,1999 2234,1999 2254,1999 1894,2019 1914,2019 1934,2019 1954,2019 1974,2019 1994,2019 2014,2019 2034,2019 2054,2019 2074,2019 2094,2019 2114,2019 2134,2019 2154,2019 2174,2019 2194,2019 2214,2019 2234,2019 2254,2019 2274,2019 2114,2079 2134,2079 2154,2079 2174,2079 2194,2079 2214,2079 2234,2079 1734,2084 1754,2084 1774,2084 1794,2084 1814,2084 1934,2089 1954,2089 1974,2089 1994,2089 2014,2089 2034,2089 2054,2089 2074,2089 2094,2089 2114,2099 2134,2099 2154,2099 2174,2099 2194,2099 2214,2099 1734,2104 1754,2104 1774,2104 1794,2104 1814,2104 1734,2124 1754,2124 1774,2124 1794,2124 1814,2124 1874,2124 1734,2144 1754,2144 1774,2144 1794,2144 1814,2144 1874,2144 1894,2144 2444,2344 2443.82,2363.82
  other v2: 2565.12,2028.53 1494,2644 1514,2644 1479,2669 1479,2689 1479,2709 1479,2729 1479,2749
  other v3: 1894,2289 1894,2344
M0_SOA: U2.23 U3.5 | length 125.6
  Top Layer w10: v1(2140.84,2218.24) 2141.61,2219 2162.92,2219 U3.5
  Bottom Layer w10: v1(2140.84,2218.24) 2143.4,2220.79 2143.4,2220.9 2153.92,2231.43 2153.92,2231.77 U2.23
M0_SOB: U2.22 U3.6 | length 127.1
  Top Layer w10: v1(2159,2199) 2160.91,2200.91 2172.68,2200.91 U3.6
  Bottom Layer w10: v1(2159,2199) 2160.53,2200.53 2160.53,2210.42 2174,2223.89 U2.22
M0_SOC: U2.21 U3.7 | length 127.4
  Top Layer w10: v1(2179,2179) 2179,2179.41 U3.7
  Bottom Layer w10: v1(2179,2179) 2179,2201.17 U2.21
M0_SPA: Q5.2 Q5.3 Q5.4 Q5.5 Q5.6 R25.2 U2.9 | length 414.7
  Bottom Layer w6: U2.9 2354.36,2404.36 2354.36,2445.66 2362,2453.3 2362,2595.38 2380.62,2614 2464,2614 2478.81,2599.19 2478.81,2555.68 R25.2
M0_SPB: Q6.2 Q6.3 Q6.4 Q6.5 Q6.6 R26.2 U2.12 | length 243.1
  Bottom Layer w6: R26.2@2496.17,2368.99 R26.2@2501.16,2364
  Bottom Layer w10: U2.12 2338.36,2321.44 2357.43,2302.37 2462.18,2302.37 2495.5,2335.69 2495.5,2368.99 R26.2 ; Q6.5@2609.01,2301.42 Q6.5@2609.01,2315.2
M0_SPC: Q7.2 Q7.3 Q7.4 Q7.5 Q7.6 R27.2 U2.19 | length 405.6
  Bottom Layer w10: U2.19 2257.4,2207.41 2257.4,2174.39 2390.81,2040.98 2460.33,2040.98 2494,2007.31 R27.2
NetC3_2: C3.2 R7.2 S1.2 U3.4 | length 1131.7
  Top Layer w10: v1(2134,2189) 2119,2204 2119,2229 2129,2239 2155.08,2239 U3.4 ; S1.2@2544.12,2336.69 2683.88,2336.69 S1.2@2688.29,2332.28 ; R7.2@2642,2206.05 R7.2 2642,2209.8 2680.2,2248 2684,2248 C3.2 S1.2@2689,2331.57 ; 2690,2274.17 2711.14,2274.17 v2(2712.67,2275.7)
  Sign w10: v1(2134,2189) 2164,2159 2235,2159 2261.97,2132.03 2569,2132.03 v2(2712.67,2275.7)
NetC4_1: C4.1 U2.3 | length 137.5
  Bottom Layer w6: U2.3 2254.73,2474.48 2263.03,2482.78 2263.03,2566.59 2282,2585.55 2289,2592.55 C4.1
NetC4_2: C4.2 U2.4 | length 100.5
  Bottom Layer w6: U2.4 2268.65,2460.57 2276.96,2468.88 2276.96,2536.04 2280.47,2539.55 2282,2539.55 2289,2546.55 C4.2
NetC6_1: C6.1 U2.1 | length 221.1
  Bottom Layer w6: U2.1 2226.89,2502.33 2234,2509.44 2234,2634.02 2282,2682.02 2282,2688 C6.1
NetC6_2: C6.2 U2.2 | length 184.7
  Bottom Layer w6: U2.2@2247.07,2491.95 2247.07,2494.67 2249.11,2496.71 2249.11,2624.11 2264.5,2639.5 2282,2639.5 2289,2646.5 C6.2
NetC7_2: C7.2 L1.2 U3.15 | length 129.7
  Top Layer w10: U3.15 2383.6,2314.19 2418.79,2279 C7.2 ; L1.2 L1.2@2484,2250.13
  Top Layer w14: C7.2 2420.77,2280.77 2453.36,2280.77 L1.2@2484,2250.13
NetC9_1: C9.1 U4.4 | length 49.7
  Top Layer w10: C9.1 1741.91,2562.19 1742.82,2563.09 U4.4
NetC9_2: C9.2 L2.1 U4.6 | length 216
  Top Layer w14: C9.2 1648.43,2512.19 L2.1 1665.25,2519 1757.34,2519 1768.41,2507.93 U4.6
NetC18_2: C18.2 U4.2 | length 72.7
  Top Layer w10: U4.2 1794,2607.75 1805.93,2619.69 1808.43,2619.69 1813.43,2624.69 C18.2
NetL3_1: L3.1 U5.3
NetLED1_1: LED1.1 Q1.2 | length 106.6
  Top Layer w14: Q1.2 2614.55,2614 LED1.1
NetLED2_1: LED2.1 R9.2 | length 86.8
  Top Layer w14: R9.2 2579,2686.5 2582,2689.5 2584.5,2689.5 2604,2709 LED2.1
NetQ1_3: Q1.3 R10.1 | length 226.1
  Top Layer w14: Q1.3 2478.48,2583.38 2454.62,2583.38 2439,2599 2439,2674 2455,2690 2512.8,2690 2513.3,2689.5 2521,2689.5 2524,2686.5 R10.1
NetQ2_1: Q2.1 R11.1 | length 402.6
  Bottom Layer w10: R11.1 2496.5,2694 2501.5,2699 2501.5,2701.5 2558,2758 2731,2758 2812.09,2676.91 2824.04,2676.91 Q2.1
NetQ3_1: Q3.1 R12.1 | length 458.1
  Bottom Layer w10: R12.1 2496.5,2196.01 2535.5,2157 2728,2157 2791,2220 2862.12,2220 2888.93,2246.81 Q3.1@2898.77,2246.81
NetQ4_1: Q4.1 R13.1 | length 377.8
  Bottom Layer w10: R13.1@2491.86,2139 2730.67,2139 2814.2,2055.48 2814.2,2053 2815.99,2051.2 Q4.1@2831.83,2051.2
NetQ5_1: Q5.1 R18.1 | length 129.8
  Bottom Layer w10: R18.1 2498.26,2643.26 2513.46,2643.26 2542.86,2672.66 Q5.1@2609.89,2672.66
NetQ6_1: Q6.1 R19.1 | length 217.9
  Bottom Layer w10: R19.1 2516,2279 2571.71,2223.29 2647.43,2223.29 2658.3,2234.17 2658.3,2239.29 2666.1,2247.09 Q6.1@2675.94,2247.09
NetQ7_1: Q7.1 R20.1 | length 123.7
  Bottom Layer w14: R20.1@2496.4,2066.4 R20.1 2586.36,2064 2599.16,2051.2 Q7.1@2609,2051.2
NetR2_2: R2.2 U3.31 | length 57
  Top Layer w10: R2.2 2138,2416 2142.4,2416 U3.31
NetR6_1: R6.1 U2.30 | length 58.7
  Bottom Layer w10: R6.1 2014,2316 2019,2321 2048.29,2321 U2.30
NetR21_2: R21.2 U4.3 | length 65.2
  Top Layer w10: R21.2 1767.5,2623.11 1767.5,2564.91 U4.3
NetR22_1: R22.1 R24.2 R28.2 | length 101.3
  Top Layer w14: R28.2 R22.1 1919.2,2608.8 1919.2,2562 R24.2
NetR23_1: R23.1 R29.2 U5.5 | length 408.1
  Top Layer w14: U5.5 v2(1357.89,2375.11) ; R23.1 R29.2 1514,2501.5 1517,2504.5 1517.9,2504.5 1549,2535.6 v2(1549,2569)
  GND w14: v2(1357.89,2375.11) 1358.66,2375.88 1358.66,2378.66 v2(1549,2569)
NetR24_1: R24.1 U4.1 | length 58.9
  Top Layer w10: U4.1 1819.59,2559.91 1820.5,2559 R24.1
nFAULT: R5.2 U2.25 U3.10 | length 420.4
  Top Layer w10: U3.10 2313.8,2243.87 2329,2228.67 2329,2187.16 2322,2180.16 v1(2322,2178)
  Sign w10: v1(2101,2238) 2102.53,2239.53 2108.19,2239.53 2109.54,2240.88 2151.12,2240.88 2215.76,2176.24 2314.59,2176.24 2314.81,2176.47 2320.47,2176.47 v1(2322,2178)
  Bottom Layer w10: R5.2 2055.77,2227.23 2088.07,2227.23 2098.84,2238 v1(2101,2238) 2102.53,2239.53 2106.01,2239.53 U2.25
SPI_MISO: H2.5 U3.27 | length 907
  Top Layer w6: U3.27 2230.28,2443.03 2220,2453.31 2220,2510 2276,2566 2425,2566 2502,2489 2888.96,2489
  Top Layer w8: 2888.96,2489 2918.13,2518.17
  Top Layer w10: 2918.13,2518.17 H2.5
SPI_MOSI: H2.6 U3.28 | length 885.3
  Top Layer w6: U3.28 2216.36,2429.11 2206.25,2439.23 2206.25,2513.22 2271.03,2578 2430.5,2578 2506.5,2502 2850.79,2502
  Top Layer w8: 2850.79,2502 2868.92,2520.14
  Top Layer w10: 2868.92,2520.14 H2.6
SPI_NSS: H2.3 U3.25 | length 952.7
  Top Layer w6: U3.25 2258.12,2470.87 2244,2484.99 2244,2499.03 2286.97,2542 2414,2542 2493,2463 2965.32,2463
  Top Layer w8: 2965.32,2463 3016.56,2514.24
  Top Layer w10: 3016.56,2514.24 H2.3
SPI_SCK: H2.4 U3.26 | length 929.6
  Top Layer w6: U3.26 2244.2,2456.95 2232,2469.15 2232,2504 2282,2554 2420,2554 2498,2476 2927.14,2476
  Top Layer w8: 2927.14,2476 2967.34,2516.2
  Top Layer w10: 2967.34,2516.2 H2.4
State_LED: Q1.1 U3.11 | length 648.5
  Top Layer w10: U3.11 2350.47,2235.75 2350.47,2167.48 2343.01,2160.02 v1(2343.01,2157.86)
  Sign w10: v1(2343.01,2157.86) 2343.01,2160.02 2365.99,2183 2473,2183 2564,2274 v1(2564,2539)
SWCLK: CN2.3 R15.1 U3.24 | length 401.9
  Top Layer w10: v1(2295.92,2488.92) 2297.45,2487.39 2297.45,2484.94 2307.11,2475.28 2307.11,2474.55 U3.24
  Top Layer w14: R15.1 2019,2531.5 2043.23,2555.73 2043.23,2563.23 v2(2044,2564)
  Sign w10: v2(2044,2564) 2046.16,2564 2053.08,2570.91 2152.42,2570.91 2234.41,2488.92 v1(2295.92,2488.92)
  Bottom Layer w10: CN2.3 2044,2601.42 v2(2044,2564)
SWDIO: CN2.4 R14.2 U3.23 | length 503.2
  Top Layer w10: v1(2296,2517.55) 2298.16,2517.55 2305.75,2509.97 2305.87,2509.97 2325.91,2489.93 2325.91,2466.24 2313.79,2454.13 U3.23
  Top Layer w14: R14.2 1974,2531.5 1993.23,2550.73 1993.23,2568.23 v2(1994,2569)
  Sign w10: v2(1994,2569) 2012.62,2587.62 2163.79,2587.62 2233.85,2517.55 v1(2296,2517.55)
  Bottom Layer w10: CN2.4 v2(1994,2569) v2(1994,2569)
VCC: C10.2 C11.2 C12.2 C20.2 CN3.2 Q2.7 Q2.8 Q2.9 Q2.10 Q3.7 Q3.8 Q3.9 Q3.10 Q4.7 Q4.8 Q4.9 Q4.10 R3.2 R6.2 R21.1 U2.5 U4.7 | length 1885.1
  Top Layer w14: R21.1 v3(1763.43,2713.43) ; U4.7 C12.2 1831.29,2419 1836.29,2414 v3(1839,2414)
  GND w14: v3(1763.43,2713.43) 1763.43,2489.57 v3(1839,2414)
  Sign w6: 2781.61,2744 2784,2744
  Sign w14: v1(2443.3,2736.87) 2774.49,2736.87 2781.61,2744
  Bottom Layer w6: U2.5 2282.97,2443.93 2314,2474.96 2314,2627.2 2422.28,2735.48 2441.91,2735.48 v1(2443.3,2736.87)
  Bottom Layer w10: 1839,2074 1865.6,2074 1997.1,2205.5 1997.1,2246.4 2014,2263.3 R6.2
  Bottom Layer w14: v6(1839,1994) 1839,2074 v3(1839,2414)
  other v1: 2784,1854 2854,1854 2874,1854 2949,1854 2969,1854 2989,1854 3009,1854 3029,1854 3049,1854 3069,1854 3089,1854 3109,1854 2784,1874 2854,1874 2874,1874 2949,1874 2969,1874 2989,1874 3009,1874 3029,1874 3049,1874 3069,1874 3089,1874 3109,1874 2844,2089 2864,2089 2884,2089 2904,2089 2924,2089 2844,2109 2864,2109 2884,2109 2844,2129 2864,2129 2884,2129 2904,2129 2924,2129 2844,2149 2864,2149 2884,2149 2904,2149 2924,2149 2804,2169 2824,2169 2844,2169 2864,2169 2884,2169 2904,2169 2924,2169 2844,2189 2864,2189 2884,2189 2919,2419 2939,2419 2959,2419 2818,2420 2838,2420 2858,2420 2878,2420 2898,2420 2848,2438 2868,2438 2888,2438 2789,2439 2939,2439 2959,2439 3118.92,2644.16 3089,2664 3109,2664 3069,2684 3089,2684 3109,2684 2858,2704 2878,2704 2900,2704 2920,2704 2944,2704 2963,2704 2983,2704 3004,2704 3029,2704 3049,2704 3069,2704 3089,2704 3109,2704 2858,2725 2878,2725 2944,2725 2963,2725 2983,2725 3004,2725 2858,2746 2879,2746 2944,2746 2963,2746 2983,2746 3004,2746
VCC_ADC: R3.1 R4.2 U3.8 | length 261
  Top Layer w10: U3.8 2258.12,2229.96 2244.42,2216.26 2244.42,2183.58 2346.5,2081.5 2349,2081.5 2354,2076.5 R4.2
  Top Layer w14: R3.1 R4.2
pads on no net: CN1.3 CN1.4 CN2.5 CN2.6 H2.8 U3.3 U3.29 U3.30 U4.8

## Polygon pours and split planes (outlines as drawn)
DGND on Top Layer "Top Layer-DGND" (solid, remove dead copper, pour order 79): 1954,2589 1954,2524 1979,2499 1999,2499 1999,2429 1999,2239 2069,2169 2259,2169 2324,2104 2384,2104 2384,2009 2714,2009 2769,2064 2769,2649 2824.71,2649 2825.77,2647.94 2825.77,2764 1954,2764
M0_SNA on Top Layer "M0_SNA_L01_P061" (solid, pour order 61): 1714,2059 1829,2059 1899,1989 2269,1989 2304,2024 2304,2109 2149,2109 2109,2109 2059,2109 1934,2234 1714,2234
VCC on Top Layer "VCC_L01_P075" (solid, remove dead copper, pour order 75): 1714,2049 1824,2049 1894,1979 2274,1979 2289,1994 2474,1994 2724,1994 2784,2054 2784,2764 3129,2764 3129,2714 3129,1844 1714,1844
+3.3V on Top Layer "+3.3V_L01_P080" (solid, remove dead copper, pour order 80): 1334,2764 1449,2764 1449,2649 1484,2614 1484,2534 1444,2534 1429,2549 1334,2549
NetL3_1 on Top Layer "NETL3_1_L01_P081" (solid, remove dead copper, pour order 81): 1334,2539 1424,2539 1434,2529 1434,2484 1449,2469 1484,2469 1484,2439 1424,2439 1389,2474 1334,2474
5V on Top Layer "5V_L01_P082" (solid, remove dead copper, pour order 82): 1334,2464 1334,2424 1374,2424 1404,2394 1404,2359 1714,2359 1714,2269 1804,2269 1804,2374 1739,2374 1704,2409 1704,2459 1599,2459 1599,2399 1589,2389 1429,2389 1429,2419 1384,2464
NetC9_2 on Top Layer "NETC9_2_L01_P083" (solid, remove dead copper, pour order 83): 1599,2474 1704,2474 1704,2504 1709,2509 1754,2509 1759,2504 1759,2444 1774,2444 1774,2514 1759,2529 1704,2529 1699,2534 1669,2534 1669,2574 1599,2574
M0_SNA on Top Layer "M0_SNA_L01_P084" (solid, remove dead copper, pour order 84): 1464,2764 1464,2659 1499,2624 1499,2534 1514,2534 1529,2549 1529,2584 1539,2594 1554,2594 1569,2579 1569,2474 1554,2459 1499,2459 1499,2429 1494,2424 1439,2424 1439,2404 1579,2404 1589,2414 1589,2589 1554,2624 1554,2764
M0_SNA on Bottom Layer "M0_SNA_L04_P064" (solid, pour order 64): 1719,2764 2424,2764 2424,2744 2309,2629 2284,2629 2199,2544 2114,2544 1994,2424 1994,2169 2034,2129 2129,2129 2164,2164 2225,2164 2449,1940 2449,1843 1719,1843
M0_SNA on Bottom Layer "M0_SNA_L04_P063" (solid, pour order 63): 2454,2604 2464,2594 2464,2324 2454,2314 2379,2314 2379,2594 2389,2604
M0_SPC on Bottom Layer "M0_SPC_L04_P066" (solid, remove dead copper, pour order 66): 2546.45,1843 2546.45,1898.35 2690.45,1898.35 2705.45,1913.35 2705.45,2064.35 2643,2064.35 2643,2026 2464.45,2026 2464.45,1843
M0_SPB on Bottom Layer "M0_SPB_L04_P067" (solid, remove dead copper, pour order 67): 2475,2306 2475,2447 2523,2447 2578,2392 2703,2392 2703,2275 2640,2275 2640,2241 2636,2237 2580,2237 2511,2306
M0_SPA on Bottom Layer "M0_SPA_L04_P068" (solid, remove dead copper, pour order 68): 2475,2462 2520,2462 2569,2511 2707,2511 2707,2687 2647,2687 2647,2647 2538,2647 2518,2627 2518,2619 2469,2619 2464,2614 2475,2603
M0_SH_B on Bottom Layer "Bottom Layer-M0_SH_B" (solid, remove dead copper, pour order 69): 2929,2272 2943,2258 2943,2229 3129,2229 3129,2354 2985,2354 2985,2400 2795,2400 2744,2451 2552,2451 2552,2435 2584,2403 2713,2403 2713,2229 2693,2209 2570,2209 2570,2170 2718,2170 2780,2232 2855,2232 2866,2243 2866,2272
VCC on Bottom Layer "VCC_L04_P070" (solid, remove dead copper, pour order 70): 2754,2138 2754,2158 2800,2204 2935,2204 2935,2079 2813,2079
M0_SH_A on Bottom Layer "M0_SH_A_L04_P071" (solid, remove dead copper, pour order 71): 2552,2464 2552,2476 2575,2499 2718,2499 2718,2698 2548,2698 2541,2705 2541,2720 2567,2746 2722,2746 2796,2672 2796,2645 2865,2645 2865,2688 3028,2688 3129,2587 3129,2369 2995,2369 2995,2454.87 2933.87,2516 2798,2516 2745.64,2463.64
VCC on Bottom Layer "VCC_L04_P072" (solid, remove dead copper, pour order 72): 2770,2473 2770,2440 2799,2411 2984,2411 2984,2447 2927,2504 2801,2504
VCC on Bottom Layer "VCC_L04_P073" (solid, remove dead copper, pour order 73): 2817,2694 2764,2747 2764,2759 3128,2759 3128,2622 3109,2622 3037,2694 2925,2694
VCC on Bottom Layer "VCC_L04_P074" (solid, remove dead copper, pour order 74): 2758,1867 2777,1886 3124,1886 3124,1844 2758,1844
M0_SH_C on Bottom Layer "Bottom Layer-M0_SH_C" (solid, remove dead copper, pour order 77): 2555.45,1842 2744.45,1842 2744.45,1868.35 2772.45,1896.35 3129,1896.35 3129,2214 2944.45,2214 2944.45,2068.35 2860.45,2068.35 2860.45,2027.35 2795.45,2027.35 2795.45,2062.55 2734,2124 2566.1,2124 2537,2094.9 2537,2087.92 2552.57,2072.35 2709.45,2072.35 2714.45,2067.35 2714.45,1907.35 2697.45,1890.35 2555.45,1890.35
M0_SNA on Sign "NONET_L-01_P-001" (solid, remove dead copper, pour order 65): 2724,2759 1724,2759 1724,1850 2724,1850
VCC on Sign "VCC_L03_P076" (solid, remove dead copper, pour order 76): 2739,2759 2739,1849 3129,1849 3129,2759
AGND on Sign "AGND_L03_P062" (solid, pour order 62): 1969,2114 1969,2354 2009,2394 2009,2494 1924,2494 1924,2114
M0_SNA on GND "GND-M0_SNA" (solid, remove dead copper, pour order 85): 1724,1851 2752.78,1851 2752.78,2760.33 1727.54,2763.99 1727.53,2763.99 1724,2764 1724,2763.99 1334.01,2763.99 1334,2764 1334,2359 1724,2359
VCC on GND "VCC_L02_P078" (solid, remove dead copper, pour order 78): 3126.8,1844.94 3126.8,2762.27 2764.59,2762.27 2764.59,1844.94

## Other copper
Top Layer:
  pour cut-out: 2780.34,2628.57 2780.34,2413.46 3085.07,2413.46 3129,2457.39 3129,2628.57
  pour cut-out: 2429,2324 2299,2194 2259.61,2194 2157.01,2296.6 2174,2313.59 2174,2389 2264,2479

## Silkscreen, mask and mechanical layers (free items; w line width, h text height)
Mechanical 1:
  lines w10: 1323.65,2348.88 1323.65,2778.02 2130.73,2778.02 3144.51,2778.02 3516.56,2778.02 3516.56,2553.61 3159.74,2553.61 3138.61,2532.47 3138.61,2050.37 3161.42,2027.56 3516.56,2027.56 3516.56,1834.03 2930.26,1834.03 1701.6,1834.03 1701.6,2348.88 1504.75,2348.88 1323.65,2348.88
